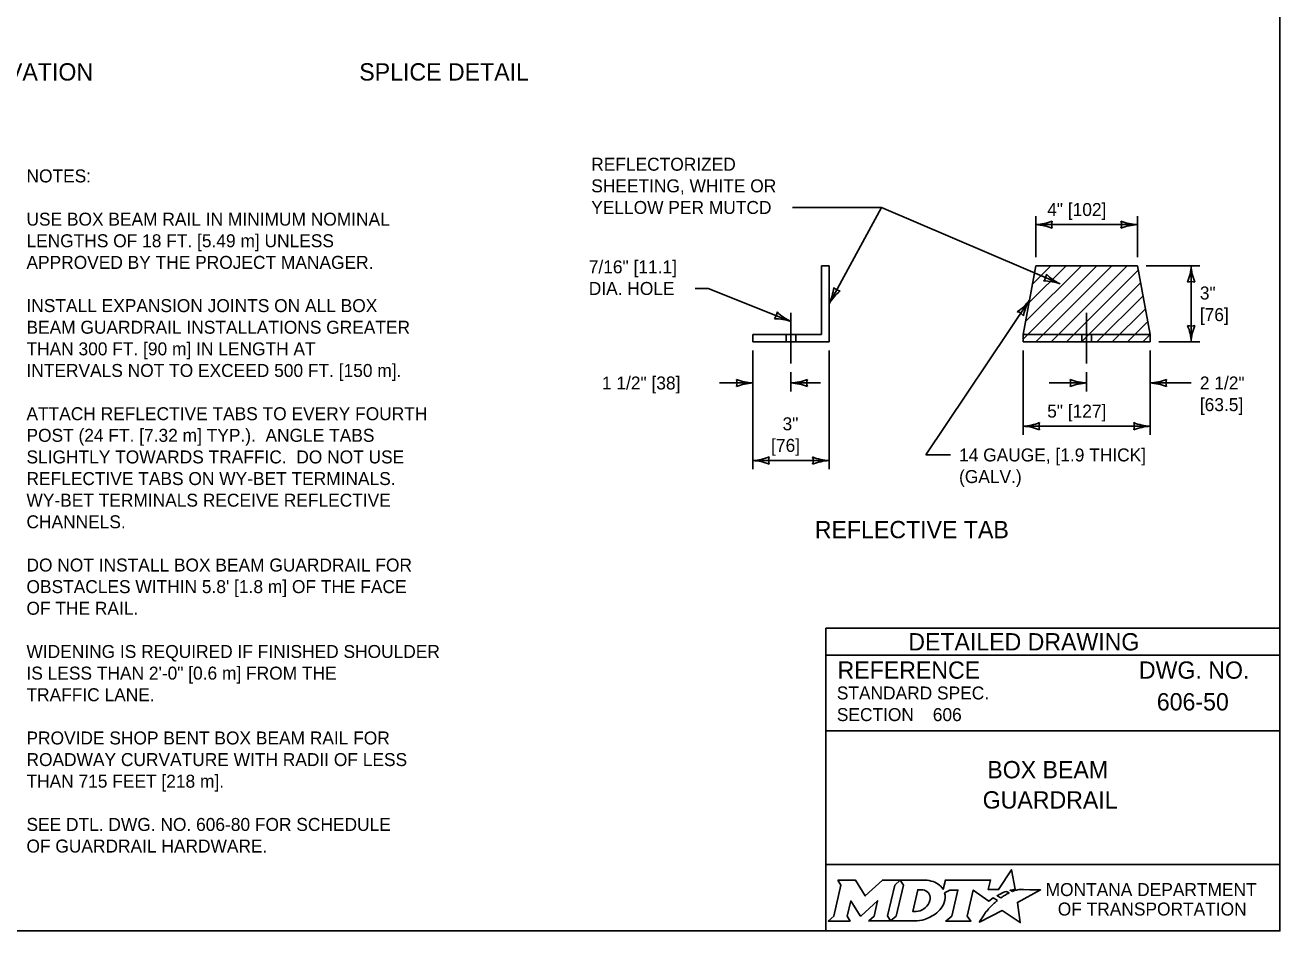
# Model space of a CAD drawing. Extents: x 49991.4 to 50021, y 49987.6 to 50011.4.
# Drawn here: x 50015.13 to 50020.94, y 49999.89 to 50004.08 of the extents above; entities that cross this region are included whole.
import ezdxf

# ---------------------------------------------------------------- set-up
doc = ezdxf.new("R2010")
doc.units = 0
for name, color, linetype in [('Default', 7, 'Continuous'), ('Level 1', 7, 'Continuous'), ('Level 2', 7, 'Continuous'), ('Level 3', 7, 'Continuous'), ('Level 4', 7, 'Continuous'), ('Level 5', 7, 'Continuous')]:
    doc.layers.add(name, color=color, linetype=linetype)

msp = doc.modelspace()

# ---------------------------------------------------------------- linework, layer by layer
at = {"layer": 'Default'}
for points in [[(50019.7003, 50000.0679), (50019.69, 50000.0735), (50019.7016, 50000.0763), (50019.7132, 50000.0783), (50019.6958, 50000.1684), (50019.6363, 50000.0771), (50019.589, 50000.0764), (50019.5993, 50000.1205), (50019.3901, 50000.1206), (50019.38, 50000.0781), (50019.3742, 50000.0864)], [(50018.8933, 50000.1206), (50018.9074, 50000.0972), (50018.8739, 49999.9539), (50018.8482, 49999.9314), (50018.9498, 49999.9314), (50018.9363, 49999.9542), (50018.9525, 50000.0243), (50018.9962, 49999.9553), (50019.0015, 49999.9553), (50019.0766, 50000.0248), (50019.0602, 49999.9537), (50019.0355, 49999.9317), (50019.1371, 49999.9317), (50019.1233, 49999.955), (50019.1565, 50000.0974)], [(50019.1565, 50000.0974), (50019.1818, 50000.1206), (50019.0994, 50000.1206), (50019.0198, 50000.0476), (50018.9753, 50000.1203), (50018.8933, 50000.1206)], [(50019.2954, 50000.1206), (50019.1818, 50000.1206), (50019.1965, 50000.0977), (50019.1626, 49999.9539), (50019.1371, 49999.9317), (50019.2477, 49999.9317)], [(50019.3194, 50000.0339), (50019.3182, 50000.0258), (50019.315, 50000.0165), (50019.3108, 50000.0083), (50019.3052, 50000.0008), (50019.2987, 49999.9939), (50019.2908, 49999.9876), (50019.2825, 49999.9829), (50019.2734, 49999.979), (50019.2643, 49999.9767), (50019.2551, 49999.9758), (50019.2392, 49999.9758), (50019.2628, 50000.0758), (50019.2788, 50000.0758), (50019.2864, 50000.0752), (50019.294, 50000.0733), (50019.3006, 50000.0703), (50019.3067, 50000.0661), (50019.3115, 50000.0611), (50019.3152, 50000.0551), (50019.3179, 50000.0489), (50019.3195, 50000.0415), (50019.3195, 50000.0385), (50019.3194, 50000.0339)], [(50019.3868, 50000.0615), (50019.4114, 50000.0746), (50019.4483, 50000.0746), (50019.4197, 49999.9541), (50019.3922, 49999.9314), (50019.5084, 49999.9314), (50019.4914, 49999.9543), (50019.5196, 50000.0745), (50019.5909, 50000.0228), (50019.612, 50000.0379), (50019.6317, 50000.027)], [(50019.5759, 49999.9711), (50019.5606, 49999.9467), (50019.5559, 49999.9392), (50019.5501, 49999.9306), (50019.5478, 49999.9263), (50019.6531, 49999.9794), (50019.737, 49999.9243), (50019.7239, 50000.017), (50019.8308, 50000.0754), (50019.7815, 50000.0762), (50019.7514, 50000.0766), (50019.7306, 50000.0769), (50019.7238, 50000.0754), (50019.7189, 50000.0742), (50019.7105, 50000.0719), (50019.7003, 50000.0679)], [(50019.6499, 50000.0403), (50019.6475, 50000.0386), (50019.6292, 50000.0482), (50019.6395, 50000.0539), (50019.6436, 50000.0561), (50019.6522, 50000.0601), (50019.6579, 50000.0627), (50019.6658, 50000.0657), (50019.6731, 50000.0684), (50019.6849, 50000.061), (50019.6809, 50000.0589), (50019.6763, 50000.0564), (50019.6721, 50000.0542), (50019.6671, 50000.0513), (50019.6652, 50000.0502), (50019.6625, 50000.0486), (50019.66, 50000.0472), (50019.6577, 50000.0456), (50019.6551, 50000.0438), (50019.6524, 50000.042), (50019.6499, 50000.0403)], [(50019.2934, 49999.939), (50019.3018, 49999.9416), (50019.3148, 49999.947), (50019.3352, 49999.958)], [(50019.5898, 49999.9872), (50019.5898, 49999.9872)]]:
    msp.add_lwpolyline(points, dxfattribs=at)
for centre, radius, start, end in [((50019.3185, 50000.0422), 0.0709, 339.53292, 15.85821), ((50019.2745, 50000.0595), 0.1183, 300.91025, 339.13831)]:
    msp.add_arc(centre, radius, start, end, dxfattribs=at)
for centre, major_axis, ratio, start_param, end_param in [((50019.2933, 50000.0732), (0.0834, -0.0037), 0.568097, 0.61298, 1.570796), ((50019.3489, 50000.0805), (0.0361, -0.0295), 0.469099, 1.225588, 1.570796), ((50019.5996, 49999.9974), (-0.0098, -0.0102), 0.016458, 3.141593, 6.279097), ((50019.6206, 50000.0173), (-0.0112, -0.0097), 0.021651, 3.157348, 6.283185), ((50019.248, 50000.08), (0, 0.1484), 0.987302, 3.139398, 3.456847), ((50019.5829, 49999.9791), (-0.00694, -0.00806), 0.008222, 0, 3.137361)]:
    msp.add_ellipse(centre, major_axis=major_axis, ratio=ratio, start_param=start_param, end_param=end_param, dxfattribs=at)
at = {"layer": 'Level 1'}
for p, q in [((50018.8173, 50002.9627), (50018.8173, 50002.6452)), ((50018.8173, 50002.9627), (50018.8523, 50002.9627)), ((50018.8523, 50002.9627), (50018.8523, 50002.6102)), ((50019.8088, 50002.9627), (50019.7501, 50002.6452)), ((50019.7501, 50002.6225), (50020.0903, 50002.9627)), ((50019.761, 50002.7041), (50020.0196, 50002.9627)), ((50019.777, 50002.7909), (50019.9489, 50002.9627)), ((50019.7931, 50002.8776), (50019.8781, 50002.9627)), ((50019.8085, 50002.6102), (50020.161, 50002.9627)), ((50020.2787, 50002.9627), (50019.8088, 50002.9627)), ((50019.8792, 50002.6102), (50020.2317, 50002.9627)), ((50020.2787, 50002.9627), (50020.3374, 50002.6452)), ((50019.9499, 50002.6102), (50020.2824, 50002.9427)), ((50020.0206, 50002.6102), (50020.2934, 50002.883)), ((50020.0913, 50002.6102), (50020.3045, 50002.8233)), ((50020.162, 50002.6102), (50020.3155, 50002.7637)), ((50020.2327, 50002.6102), (50020.3265, 50002.704)), ((50018.8173, 50002.6452), (50018.4998, 50002.6452)), ((50018.4998, 50002.6452), (50018.4998, 50002.6102)), ((50018.8523, 50002.6102), (50018.4998, 50002.6102)), ((50019.7501, 50002.6452), (50019.7501, 50002.6102)), ((50020.3374, 50002.6102), (50019.7501, 50002.6102)), ((50020.3035, 50002.6102), (50020.3374, 50002.6441)), ((50020.3374, 50002.6452), (50020.3374, 50002.6102))]:
    msp.add_line(p, q, dxfattribs=at)
msp.add_lwpolyline([(50020.9378, 50008.1646), (50009.7374, 50008.1646), (50009.7374, 49999.8856), (50020.9378, 49999.8856)], close=True, dxfattribs=at)
at = {"layer": 'Level 3'}
for p, q in [((50018.6838, 50003.2322), (50019.0944, 50003.2322)), ((50019.0944, 50003.2322), (50018.8523, 50002.7871)), ((50019.0944, 50003.2322), (50019.9212, 50002.8783)), ((50019.8088, 50003.0027), (50019.8088, 50003.1927)), ((50020.2787, 50003.0027), (50020.2787, 50003.1927)), ((50019.8088, 50003.1527), (50020.2787, 50003.1527)), ((50019.2996, 50002.0873), (50019.7795, 50002.8041)), ((50019.4136, 50002.0873), (50019.2996, 50002.0873))]:
    msp.add_line(p, q, dxfattribs=at)
for points in [[(50020.3187, 50002.9627), (50020.5674, 50002.9627)], [(50020.5274, 50002.6102), (50020.5274, 50002.9627)], [(50018.2933, 50002.8575), (50018.2933, 50002.8575), (50018.2333, 50002.8575)], [(50018.2933, 50002.8575), (50018.676, 50002.7052)], [(50020.3774, 50002.6102), (50020.5674, 50002.6102)], [(50018.4998, 50002.5702), (50018.4998, 50002.0215)], [(50018.8523, 50002.5702), (50018.8523, 50002.0215)], [(50019.7501, 50002.5702), (50019.7501, 50002.1802)], [(50020.3374, 50002.5702), (50020.3374, 50002.1802)], [(50018.676, 50002.4702), (50018.676, 50002.3802)], [(50020.0438, 50002.4702), (50020.0438, 50002.3802)], [(50018.346, 50002.4202), (50018.4998, 50002.4202)], [(50018.676, 50002.4202), (50018.8123, 50002.4202)], [(50020.0438, 50002.4202), (50019.8704, 50002.4202)], [(50020.3374, 50002.4202), (50020.5274, 50002.4202)], [(50019.7501, 50002.2202), (50020.3374, 50002.2202)], [(50018.4998, 50002.0615), (50018.8523, 50002.0615)]]:
    msp.add_lwpolyline(points, dxfattribs=at)
for centre, radius, start, end in [((50019.7973, 50003.3854), 0.233, 272.82731, 292.07716), ((50019.7996, 50002.9306), 0.2223, 67.45601, 87.63952), ((50019.937, 50003.1527), 0.0548, 162.13882, 197.86118), ((50020.2879, 50003.3748), 0.2223, 247.45601, 267.63952), ((50020.1505, 50003.1527), 0.0548, 342.13882, 17.86118), ((50020.2902, 50002.92), 0.233, 92.82731, 112.07716), ((50020.2947, 50002.9742), 0.233, 337.92284, 357.17269), ((50020.7495, 50002.9719), 0.2223, 182.36048, 202.54399), ((50019.8033, 50002.9288), 0.0548, 318.96598, 354.68834), ((50019.8402, 50002.6599), 0.233, 69.65447, 88.90432), ((50020.017, 50003.0789), 0.2223, 224.28317, 244.46668), ((50018.6424, 50002.8881), 0.233, 334.28715, 353.537), ((50019.0431, 50002.6729), 0.2223, 128.91585, 149.09936), ((50018.9136, 50002.8997), 0.0548, 223.59866, 259.32102), ((50020.5274, 50002.8345), 0.0548, 72.13882, 107.86118), ((50019.5999, 50002.9352), 0.2223, 303.65156, 323.83507), ((50019.6, 50002.9353), 0.2223, 303.65156, 323.83507), ((50019.9792, 50002.6841), 0.233, 149.02286, 168.27271), ((50019.9792, 50002.6842), 0.233, 149.02286, 168.27271), ((50018.5569, 50002.7526), 0.0548, 320.43923, 356.16159), ((50018.7666, 50002.9082), 0.2223, 225.75642, 245.93993), ((50019.7081, 50002.6974), 0.0548, 38.33437, 74.05673), ((50019.7081, 50002.6975), 0.0548, 38.33437, 74.05673), ((50018.6006, 50002.4847), 0.233, 71.12772, 90.37757), ((50020.3053, 50002.601), 0.2223, 2.36048, 22.54399), ((50020.5274, 50002.7384), 0.0548, 252.13882, 287.86118), ((50020.7601, 50002.5987), 0.233, 157.92284, 177.17269), ((50018.509, 50002.6423), 0.2223, 247.45601, 267.63952), ((50018.3716, 50002.4202), 0.0548, 342.13882, 17.86118), ((50018.6645, 50002.6529), 0.233, 272.82731, 292.07716), ((50018.8042, 50002.4202), 0.0548, 162.13882, 197.86118), ((50019.9156, 50002.4202), 0.0548, 342.13882, 17.86118), ((50020.0553, 50002.6529), 0.233, 247.92284, 267.17269), ((50020.3259, 50002.6529), 0.233, 272.82731, 292.07716), ((50020.4656, 50002.4202), 0.0548, 162.13882, 197.86118), ((50018.5113, 50002.1875), 0.233, 92.82731, 112.07716), ((50018.6668, 50002.1981), 0.2223, 67.45601, 87.63952), ((50020.053, 50002.1981), 0.2223, 92.36048, 112.54399), ((50020.3282, 50002.1981), 0.2223, 67.45601, 87.63952), ((50019.7386, 50002.4529), 0.233, 272.82731, 292.07716), ((50019.7409, 50001.9981), 0.2223, 67.45601, 87.63952), ((50019.8783, 50002.2202), 0.0548, 162.13882, 197.86118), ((50020.3466, 50002.4423), 0.2223, 247.45601, 267.63952), ((50020.2092, 50002.2202), 0.0548, 342.13882, 17.86118), ((50020.3489, 50001.9875), 0.233, 92.82731, 112.07716), ((50018.4883, 50002.2942), 0.233, 272.82731, 292.07716), ((50018.4906, 50001.8393), 0.2223, 67.45601, 87.63952), ((50018.628, 50002.0615), 0.0548, 162.13882, 197.86118), ((50018.8615, 50002.2836), 0.2223, 247.45601, 267.63952), ((50018.7241, 50002.0615), 0.0548, 342.13882, 17.86118), ((50018.8638, 50001.8287), 0.233, 92.82731, 112.07716)]:
    msp.add_arc(centre, radius, start, end, dxfattribs=at)
at = {"layer": 'Level 4'}
for p, q in [((50018.654, 50002.6452), (50018.654, 50002.6102)), ((50018.698, 50002.6452), (50018.698, 50002.6102)), ((50020.3374, 50002.6452), (50019.7501, 50002.6452)), ((50020.0218, 50002.6452), (50020.0218, 50002.6102)), ((50020.0658, 50002.6452), (50020.0658, 50002.6102)), ((50020.9378, 50001.2856), (50018.8378, 50001.2856)), ((50018.8378, 50001.2856), (50018.8378, 49999.8856)), ((50020.9378, 50001.1606), (50018.8378, 50001.1606)), ((50020.5739, 50000.9455), (50020.5739, 50000.9455)), ((50019.3321, 50000.8861), (50019.3321, 50000.8861)), ((50020.9378, 50000.8106), (50018.8378, 50000.8106)), ((50019.8878, 50000.5615), (50019.8878, 50000.5615)), ((50020.9378, 50000.1925), (50018.8378, 50000.1925))]:
    msp.add_line(p, q, dxfattribs=at)
at = {"layer": 'Level 5'}
for points in [[(50018.676, 50002.7452), (50018.676, 50002.5102)], [(50020.0438, 50002.7452), (50020.0438, 50002.5102)]]:
    msp.add_lwpolyline(points, dxfattribs=at)

# ---------------------------------------------------------------- texts
at = {"layer": 'Default'}
for s, p in [('MONTANA DEPARTMENT', (50019.854, 50000.0468)), ('OF TRANSPORTATION', (50019.9102, 49999.9568))]:
    msp.add_text(s, height=0.06, dxfattribs=at).set_placement(p)
at = {"layer": 'Level 2'}
for s, height, p in [('ELEVATION', 0.08, (50014.8472, 50003.8194)), ('SPLICE DETAIL', 0.08, (50016.679, 50003.8194)), ('REFLECTORIZED', 0.06, (50017.7521, 50003.4022)), ('NOTES:', 0.06, (50015.1395, 50003.3481)), ('SHEETING, WHITE OR', 0.06, (50017.7521, 50003.3022)), ('YELLOW PER MUTCD', 0.06, (50017.7521, 50003.2022)), ('4" [102]', 0.06, (50019.8613, 50003.1927)), ('USE BOX BEAM RAIL IN MINIMUM NOMINAL', 0.06, (50015.1395, 50003.1481)), ('LENGTHS OF 18 FT. [5.49 m] UNLESS', 0.06, (50015.1395, 50003.0481)), ('APPROVED BY THE PROJECT MANAGER.', 0.06, (50015.1395, 50002.9481)), ('7/16" [11.1]', 0.06, (50017.7407, 50002.9275)), ('DIA. HOLE', 0.06, (50017.7407, 50002.8275)), ('3"', 0.06, (50020.5674, 50002.8065)), ('INSTALL EXPANSION JOINTS ON ALL BOX', 0.06, (50015.1395, 50002.7481)), ('[76]', 0.06, (50020.5674, 50002.7065)), ('BEAM GUARDRAIL INSTALLATIONS GREATER ', 0.06, (50015.1395, 50002.6481)), ('THAN 300 FT. [90 m] IN LENGTH AT', 0.06, (50015.1395, 50002.5481)), ('INTERVALS NOT TO EXCEED 500 FT. [150 m].', 0.06, (50015.1395, 50002.4481)), ('1 1/2" [38]', 0.06, (50017.8015, 50002.3902)), ('2 1/2"', 0.06, (50020.5674, 50002.3902)), ('5" [127]', 0.06, (50019.8613, 50002.2602)), ('[63.5]', 0.06, (50020.5674, 50002.2902)), ('ATTACH REFLECTIVE TABS TO EVERY FOURTH', 0.06, (50015.1395, 50002.2481)), ('3"', 0.06, (50018.6371, 50002.2015)), ('POST (24 FT. [7.32 m] TYP.).  ANGLE TABS ', 0.06, (50015.1395, 50002.1481)), ('[76]', 0.06, (50018.5842, 50002.1015)), ('SLIGHTLY TOWARDS TRAFFIC.  DO NOT USE ', 0.06, (50015.1395, 50002.0481)), ('14 GAUGE, [1.9 THICK] ', 0.06, (50019.4536, 50002.0573)), ('REFLECTIVE TABS ON WY-BET TERMINALS. ', 0.06, (50015.1395, 50001.9481)), ('(GALV.)', 0.06, (50019.4536, 50001.9573)), ('WY-BET TERMINALS RECEIVE REFLECTIVE ', 0.06, (50015.1395, 50001.8481)), ('CHANNELS.', 0.06, (50015.1395, 50001.7481)), ('REFLECTIVE TAB', 0.08, (50018.7863, 50001.702)), ('DO NOT INSTALL BOX BEAM GUARDRAIL FOR', 0.06, (50015.1395, 50001.5481)), ("OBSTACLES WITHIN 5.8' [1.8 m] OF THE FACE ", 0.06, (50015.1395, 50001.4481)), ('OF THE RAIL.', 0.06, (50015.1395, 50001.3481)), ('WIDENING IS REQUIRED IF FINISHED SHOULDER', 0.06, (50015.1395, 50001.1481)), ('IS LESS THAN 2\'-0" [0.6 m] FROM THE ', 0.06, (50015.1395, 50001.0481)), ('TRAFFIC LANE.', 0.06, (50015.1395, 50000.9481)), ('606-50', 0.08, (50020.3683, 50000.9055)), ('606', 0.06, (50019.3321, 50000.8561)), ('PROVIDE SHOP BENT BOX BEAM RAIL FOR', 0.06, (50015.1395, 50000.7481)), ('ROADWAY CURVATURE WITH RADII OF LESS', 0.06, (50015.1395, 50000.6481)), ('BOX BEAM', 0.08, (50019.5842, 50000.5915)), ('THAN 715 FEET [218 m].', 0.06, (50015.1395, 50000.5481)), ('GUARDRAIL', 0.08, (50019.5629, 50000.4515)), ('SEE DTL. DWG. NO. 606-80 FOR SCHEDULE', 0.06, (50015.1395, 50000.3481)), ('OF GUARDRAIL HARDWARE.', 0.06, (50015.1395, 50000.2481))]:
    msp.add_text(s, height=height, dxfattribs=at).set_placement(p)
at = {"layer": 'Level 4'}
for s, height, p in [('DETAILED DRAWING', 0.0799, (50019.2188, 50001.1831)), ('REFERENCE', 0.08, (50018.8914, 50001.0522)), ('DWG. NO.', 0.08, (50020.2856, 50001.0522)), ('STANDARD SPEC.', 0.06, (50018.8881, 50000.9562)), ('SECTION', 0.06, (50018.8881, 50000.8562))]:
    msp.add_text(s, height=height, dxfattribs=at).set_placement(p)

doc.saveas('drawing.dxf')
